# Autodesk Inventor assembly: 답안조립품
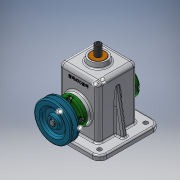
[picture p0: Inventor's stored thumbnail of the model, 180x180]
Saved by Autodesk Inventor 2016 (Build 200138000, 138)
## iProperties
Created: 2022-11
Part Number: 답안조립품
Material: 일반
Document SubType Name: Assembly
Designer: CAD03
Author: CAD03
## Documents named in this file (15)
- C:\Users\CAD03\Desktop\721106V1012\답안조립품.iam
- C:\Users\CAD03\Desktop\721106V1012\본체.ipt
- C:\Users\CAD03\Desktop\721106V1012\앞커버.ipt
- C:\Users\CAD03\Desktop\721106V1012\뒤커버.ipt
- C:\Users\CAD03\Desktop\721106V1012\볼트 M4 x 12.ipt
- C:\Users\CAD03\Desktop\721106V1012\편심축.ipt
- C:\Users\CAD03\Desktop\721106V1012\베어링 6201.ipt
- C:\Users\CAD03\Desktop\721106V1012\링크.ipt
- C:\Users\CAD03\Desktop\721106V1012\키 4 x 4 x 15.ipt
- C:\Users\CAD03\Desktop\721106V1012\슬라이드.ipt
- C:\Users\CAD03\Desktop\721106V1012\핀 5 x 18.ipt
- C:\Users\CAD03\Desktop\721106V1012\고정핀 1.2 x 10.ipt
- C:\Users\CAD03\Desktop\721106V1012\V벨트풀리.ipt
- C:\Users\CAD03\Desktop\721106V1012\멈춤나사 M3 x 8.ipt
- C:\Users\CAD03\Desktop\721106V1012\부시.ipt
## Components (11 placed, 4 different names)
1. 핀 5 x 18:1
2. 고정핀 1.2 x 10:1
3. V벨트풀리:1
4. ISO 4762 M4 x 12:1 — 강체:1
5. ISO 4762 M4 x 12:3
6. ISO 4762 M4 x 12:4
7. ISO 4762 M4 x 12:5
8. ISO 4762 M4 x 12:2 — 강체:2
9. ISO 4762 M4 x 12:6
10. ISO 4762 M4 x 12:7
11. ISO 4762 M4 x 12:8
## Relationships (2: WeldJoint 2)
- 강체:1 [WeldJoint]: ISO 4762 M4 x 12:1
- 강체:2 [WeldJoint]: ISO 4762 M4 x 12:2
